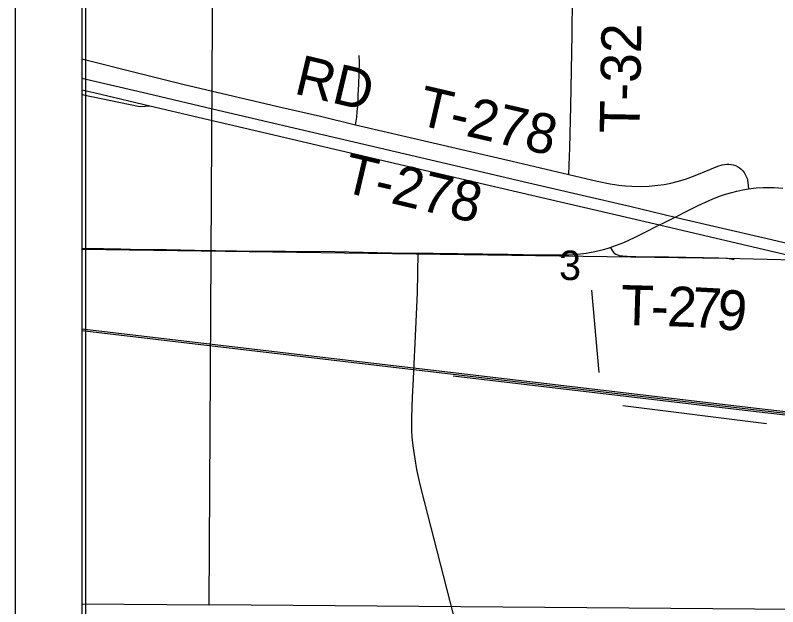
# Model space of a CAD drawing. Extents: x 63.4 to 97.4, y 0.4 to 22.4.
# Drawn here: x 65.412 to 66.497, y 15.582 to 16.424 of the extents above; entities that cross this region are included whole.
import ezdxf

# ---------------------------------------------------------------- set-up
doc = ezdxf.new("R2010")
doc.units = 0
for name, color, linetype in [('GM_X_Corporation_Text', 7, 'Continuous'), ('GM_X_County_Road', 7, 'Continuous'), ('GM_X_Minor_River', 7, 'Continuous'), ('GM_X_Rail_Line', 7, 'Continuous'), ('GM_X_Section', 7, 'Continuous'), ('GM_X_Section_Text', 7, 'Continuous'), ('GM_X_State_Route', 7, 'Continuous'), ('GM_X_Township_Road', 7, 'Continuous'), ('GM_X_Township_Road_Text', 7, 'Continuous'), ('SH_Cut_Line', 7, 'Continuous'), ('SH_Data', 7, 'Continuous')]:
    doc.layers.add(name, color=color, linetype=linetype)

msp = doc.modelspace()

# ---------------------------------------------------------------- linework, layer by layer
at = {"layer": 'GM_X_Corporation_Text'}
msp.add_lwpolyline([(65.5072, 16.585), (65.5072, 15.5868), (65.6882, 15.5852), (65.6938, 16.5825), (65.679, 16.5826)], close=True, dxfattribs=at)
at = {"layer": 'GM_X_County_Road'}
for points in [[(65.5072, 16.9001), (65.5072, 14.7073)], [(66.456, 16.1774), (66.4665, 16.1787), (66.4767, 16.1794), (66.4923, 16.1792), (66.5048, 16.1785)], [(66.259, 16.0938), (66.2629, 16.0952), (66.2782, 16.101), (66.2854, 16.1043), (66.2945, 16.1086), (66.3127, 16.1178), (66.3236, 16.1232), (66.329, 16.126), (66.3355, 16.1292), (66.3514, 16.1372), (66.3698, 16.1466), (66.3844, 16.1537), (66.4051, 16.1632), (66.416, 16.1674), (66.4233, 16.1698), (66.4322, 16.1723), (66.4394, 16.174), (66.4479, 16.1759), (66.456, 16.1774)], [(65.5072, 16.0926), (65.5377, 16.0923), (65.5625, 16.0919), (65.5905, 16.0911), (65.6277, 16.0908), (65.6681, 16.0903), (65.7271, 16.0891), (65.8669, 16.088), (65.9476, 16.0865), (65.9856, 16.086)], [(65.9856, 16.086), (66.0072, 16.086), (66.0422, 16.0853), (66.1131, 16.0844), (66.1568, 16.0834), (66.1879, 16.0833), (66.2003, 16.0836), (66.2127, 16.0845), (66.225, 16.086), (66.2373, 16.0881), (66.2494, 16.0909), (66.2546, 16.0923), (66.259, 16.0938)], [(65.9791, 15.9071), (65.9801, 15.9281), (65.9816, 15.9579), (65.9846, 16.0293), (65.9856, 16.086)], [(65.9993, 15.714), (65.9946, 15.7324), (65.9886, 15.7566), (65.984, 15.7779), (65.9812, 15.7932), (65.9785, 15.8117), (65.9773, 15.8241), (65.9768, 15.8335), (65.9768, 15.8522), (65.9777, 15.8802), (65.9791, 15.9071)], [(66.0402, 15.5547), (66.0218, 15.627), (65.9993, 15.714)]]:
    msp.add_lwpolyline(points, dxfattribs=at)
at = {"layer": 'GM_X_Minor_River'}
for points in [[(66.2323, 16.0331), (66.2428, 15.9159)], [(66.2772, 15.8691), (66.4816, 15.8431)]]:
    msp.add_lwpolyline(points, dxfattribs=at)
at = {"layer": 'GM_X_Rail_Line'}
for points in [[(65.5072, 16.0914), (66.1191, 16.083), (66.4239, 16.0787), (66.8313, 16.0688), (67.543, 16.0626), (67.9702, 16.0577), (68.6101, 16.2463), (69.1053, 16.3972), (70.1929, 16.7393), (70.2646, 16.7591), (70.3642, 16.7634), (70.5898, 16.7764), (70.6857, 16.8302), (70.7827, 16.8988), (71.2174, 17.2501), (71.5086, 17.4876), (71.6576, 17.6039), (72.13, 17.975), (72.3072, 18.116)], [(65.5072, 15.9783), (66.4673, 15.865), (66.8614, 15.8202)], [(65.5072, 15.9759), (66.467, 15.8627), (66.8611, 15.8179)], [(66.0355, 15.9113), (66.4667, 15.8604), (66.8342, 15.8186)]]:
    msp.add_lwpolyline(points, dxfattribs=at)
at = {"layer": 'GM_X_Section'}
msp.add_lwpolyline([(66.6878, 16.5693), (66.716, 16.5687), (66.7072, 15.5775), (66.7036, 15.5772), (65.6882, 15.5852), (65.6938, 16.5825)], close=True, dxfattribs=at)
at = {"layer": 'GM_X_State_Route'}
for points in [[(65.5072, 16.3349), (65.601, 16.313), (65.701, 16.2895), (65.8797, 16.2478), (66.0402, 16.2101), (66.1432, 16.186), (66.2189, 16.1683), (66.2886, 16.152), (66.3514, 16.1372), (66.3612, 16.1349), (66.4127, 16.123), (66.4824, 16.1066), (66.9589, 15.9953)], [(65.5072, 16.3182), (65.5241, 16.3143), (65.6038, 16.2956)], [(65.5072, 16.3119), (65.5095, 16.3114), (65.5871, 16.295), (65.5904, 16.2947), (65.6038, 16.2956)], [(65.6038, 16.2956), (65.6724, 16.2794), (65.7663, 16.2577), (65.9296, 16.2191), (66.0598, 16.1888), (66.329, 16.126), (66.3474, 16.1217), (66.4927, 16.0876), (66.7984, 16.0161), (66.9588, 15.9785), (66.986, 15.9721), (67.2462, 15.9113), (67.2796, 15.9042), (67.2979, 15.9007), (67.3163, 15.8979), (67.3379, 15.8952), (67.3595, 15.8931), (67.3812, 15.8916), (67.4091, 15.8905), (67.4473, 15.8897)]]:
    msp.add_lwpolyline(points, dxfattribs=at)
at = {"layer": 'GM_X_Township_Road'}
for points in [[(66.2002, 16.1979), (66.2006, 16.211), (66.2015, 16.2358), (66.2032, 16.2948), (66.2047, 16.3974), (66.2053, 16.4502)], [(65.8965, 16.2687), (65.8975, 16.2735), (65.8983, 16.2795), (65.8991, 16.2872), (65.8997, 16.2949), (65.9003, 16.3029), (65.9005, 16.311), (65.9013, 16.3258), (65.9017, 16.342), (65.9021, 16.3575), (65.9017, 16.367)], [(65.5072, 16.3624), (65.5862, 16.3425), (65.6527, 16.326), (65.7921, 16.2933), (65.8467, 16.2808), (65.8965, 16.2687)], [(65.8965, 16.2687), (66.0072, 16.243), (66.1193, 16.2168), (66.2002, 16.1979)], [(66.2002, 16.1979), (66.2406, 16.1885), (66.2589, 16.1847), (66.2711, 16.1827), (66.2803, 16.1816), (66.2896, 16.181), (66.302, 16.1808), (66.3144, 16.1814), (66.3268, 16.1825), (66.336, 16.1837), (66.3451, 16.1854), (66.3541, 16.1877), (66.366, 16.1913), (66.3777, 16.1955), (66.4007, 16.2049), (66.4124, 16.2095), (66.4184, 16.2113), (66.4216, 16.212), (66.4247, 16.2124), (66.4279, 16.2125), (66.4311, 16.2122), (66.4342, 16.2116), (66.4373, 16.2106), (66.4402, 16.2092), (66.4429, 16.2075), (66.4454, 16.2054), (66.4477, 16.2031), (66.4497, 16.2006), (66.4513, 16.1979), (66.4527, 16.195), (66.4538, 16.192), (66.4544, 16.1898), (66.455, 16.1862), (66.456, 16.1774)], [(66.259, 16.0938), (66.2594, 16.0932), (66.2627, 16.0882), (66.2647, 16.086), (66.267, 16.0845), (66.2695, 16.0832), (66.273, 16.0822), (66.2768, 16.0821), (66.283, 16.0815), (66.2954, 16.0811), (66.3421, 16.0805), (66.3918, 16.0796), (66.4135, 16.0792), (66.4259, 16.0785), (66.4356, 16.077)]]:
    msp.add_lwpolyline(points, dxfattribs=at)
at = {"layer": 'SH_Cut_Line'}
msp.add_lwpolyline([(65.5072, 16.9001), (65.5072, 14.7073)], dxfattribs=at)
at = {"layer": 'SH_Data'}
for p, q in [((65.4123, 21.4197), (65.4123, 14.4197)), ((65.5123, 21.3197), (65.5123, 14.5197))]:
    msp.add_line(p, q, dxfattribs=at)

# ---------------------------------------------------------------- texts
at = {"layer": 'GM_X_Section_Text'}
msp.add_text('3', height=0.0419, rotation=0, dxfattribs=at).set_placement((66.1863, 16.0475))
at = {"layer": 'GM_X_Township_Road_Text'}
for s, height, rotation, p in [('T-32', 0.05682, 88.938, (66.3007, 16.2561)), ('RD', 0.05682, 346.5627, (65.8075, 16.3133)), ('T-278', 0.05682, 346.8851, (65.9822, 16.2694)), ('T-278', 0.05682, 346.7109, (65.8753, 16.1739)), ('T', 0.0568, 358.4034, (66.2737, 15.9838)), ('2', 0.0568, 357.9804, (66.3394, 15.982)), ('7', 0.0568, 356.8866, (66.3741, 15.9808)), ('9', 0.0568, 353.0538, (66.4081, 15.9789)), ('-', 0.0568, 358.3293, (66.3162, 15.9827))]:
    msp.add_text(s, height=height, rotation=rotation, dxfattribs=at).set_placement(p)

doc.saveas('drawing.dxf')
